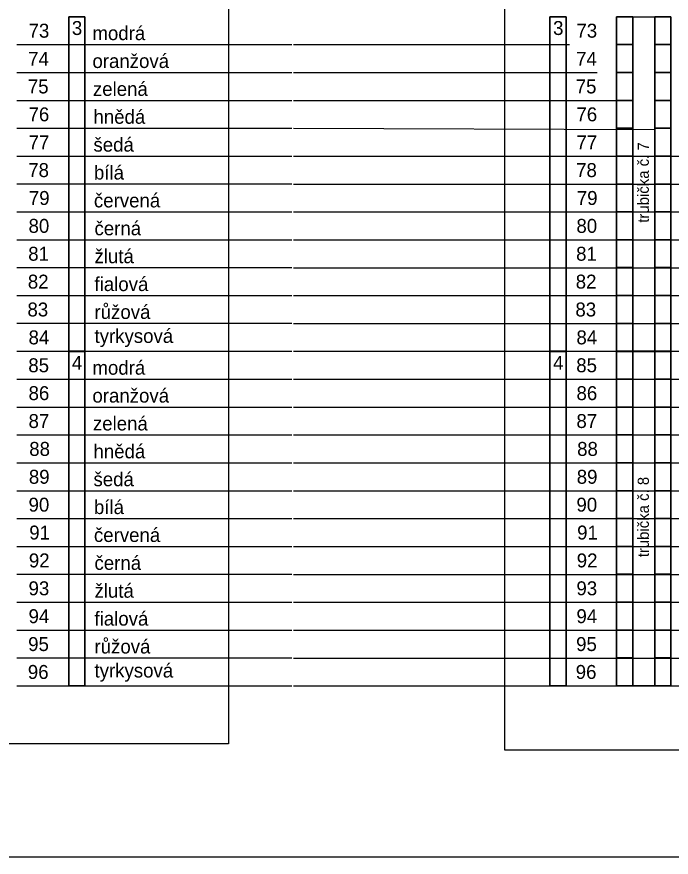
# Model space of a CAD drawing. Extents: x 1901 to 2519, y -3585 to -3154.
# Drawn here: x 2032.8 to 2115.5, y -3585 to -3478.9 of the extents above; entities that cross this region are included whole.
import ezdxf

# ---------------------------------------------------------------- set-up
doc = ezdxf.new("R2010")
doc.units = 0
doc.layers.add('rozvláknění', color=7, linetype='Continuous')
doc.layers.add('Vrstva 4', color=7, linetype='Continuous')

msp = doc.modelspace()

# ---------------------------------------------------------------- linework, layer by layer
at = {"layer": 'rozvláknění'}
for p, q in [((2032.82, -3482.38), (2067.53, -3482.38)), ((2067.76, -3482.38), (2102.61, -3482.38)), ((2032.82, -3485.9), (2067.53, -3485.9)), ((2067.76, -3485.9), (2106.13, -3485.9)), ((2032.82, -3489.42), (2067.53, -3489.42)), ((2067.76, -3489.42), (2109.65, -3489.42)), ((2032.82, -3492.94), (2067.53, -3492.94)), ((2067.76, -3492.94), (2113.34, -3493.1)), ((2032.82, -3496.46), (2067.53, -3496.46)), ((2067.76, -3496.46), (2116.69, -3496.46)), ((2032.82, -3499.97), (2067.53, -3499.97)), ((2067.76, -3499.98), (2120.21, -3499.98)), ((2032.82, -3503.49), (2067.53, -3503.49)), ((2067.76, -3503.5), (2123.73, -3503.5)), ((2032.82, -3507.01), (2067.53, -3507.01)), ((2067.76, -3507.02), (2127.25, -3507.02)), ((2032.82, -3510.53), (2067.53, -3510.53)), ((2067.76, -3510.54), (2130.77, -3510.54)), ((2032.82, -3514.05), (2067.53, -3514.05)), ((2067.76, -3514.06), (2134.29, -3514.06)), ((2032.82, -3517.56), (2067.53, -3517.56)), ((2067.76, -3517.58), (2137.81, -3517.58)), ((2032.82, -3521.1), (2067.53, -3521.1)), ((2067.76, -3521.1), (2141.33, -3521.1)), ((2032.82, -3524.62), (2067.53, -3524.62)), ((2067.76, -3524.62), (2144.85, -3524.62)), ((2032.82, -3528.14), (2067.53, -3528.14)), ((2067.76, -3528.14), (2148.37, -3528.14)), ((2032.82, -3531.66), (2067.53, -3531.66)), ((2067.76, -3531.66), (2151.89, -3531.66)), ((2032.82, -3535.18), (2067.53, -3535.18)), ((2067.76, -3535.18), (2155.41, -3535.18)), ((2032.82, -3538.7), (2067.53, -3538.7)), ((2067.76, -3538.7), (2215.14, -3538.7)), ((2032.82, -3542.21), (2067.53, -3542.21)), ((2067.76, -3542.22), (2218.66, -3542.22)), ((2032.82, -3545.73), (2067.53, -3545.73)), ((2067.76, -3545.74), (2222.18, -3545.74)), ((2032.82, -3549.25), (2067.53, -3549.25)), ((2067.76, -3549.26), (2225.7, -3549.26)), ((2032.82, -3552.77), (2067.53, -3552.77)), ((2067.76, -3552.78), (2229.22, -3552.78)), ((2032.82, -3556.29), (2067.53, -3556.29)), ((2067.76, -3556.3), (2232.74, -3556.3)), ((2032.82, -3559.8), (2067.53, -3559.8)), ((2067.76, -3559.82), (2236.26, -3559.82)), ((2032.82, -3563.34), (2067.53, -3563.34)), ((2067.76, -3563.34), (2239.78, -3563.34))]:
    msp.add_line(p, q, dxfattribs=at)
for points in [[(2014.87, -3178.54), (2059.52, -3178.54), (2059.52, -3570.66), (2014.87, -3570.66)], [(2094.46, -3178.54), (2128.46, -3178.54), (2128.46, -3571.47), (2094.46, -3571.47)], [(2041.39, -3563.34), (2039.35, -3563.34), (2039.35, -3478.87), (2041.39, -3478.87)], [(2041.39, -3521.08), (2039.35, -3521.08), (2039.35, -3478.87), (2041.39, -3478.87)], [(2102.19, -3521.08), (2100.14, -3521.08), (2100.14, -3478.87), (2102.19, -3478.87)], [(2108.57, -3478.87), (2110.61, -3478.87), (2110.61, -3482.38), (2108.57, -3482.38)], [(2108.57, -3478.87), (2110.61, -3478.87), (2110.61, -3482.38), (2108.57, -3482.38)], [(2110.61, -3478.87), (2113.39, -3478.87), (2113.39, -3521.08), (2110.61, -3521.08)], [(2113.39, -3478.87), (2115.43, -3478.87), (2115.43, -3482.38), (2113.39, -3482.38)], [(2113.39, -3478.87), (2115.43, -3478.87), (2115.43, -3482.38), (2113.39, -3482.38)], [(2108.57, -3482.38), (2110.61, -3482.38), (2110.61, -3485.9), (2108.57, -3485.9)], [(2108.57, -3482.38), (2110.61, -3482.38), (2110.61, -3485.9), (2108.57, -3485.9)], [(2113.39, -3482.38), (2115.43, -3482.38), (2115.43, -3485.9), (2113.39, -3485.9)], [(2113.39, -3482.38), (2115.43, -3482.38), (2115.43, -3485.9), (2113.39, -3485.9)], [(2108.57, -3485.9), (2110.61, -3485.9), (2110.61, -3489.42), (2108.57, -3489.42)], [(2108.57, -3485.9), (2110.61, -3485.9), (2110.61, -3489.42), (2108.57, -3489.42)], [(2113.39, -3485.9), (2115.43, -3485.9), (2115.43, -3489.42), (2113.39, -3489.42)], [(2113.39, -3485.9), (2115.43, -3485.9), (2115.43, -3489.42), (2113.39, -3489.42)], [(2108.57, -3489.42), (2110.61, -3489.42), (2110.61, -3492.94), (2108.57, -3492.94)], [(2108.57, -3489.42), (2110.61, -3489.42), (2110.61, -3492.94), (2108.57, -3492.94)], [(2113.39, -3489.42), (2115.43, -3489.42), (2115.43, -3492.94), (2113.39, -3492.94)], [(2113.39, -3489.42), (2115.43, -3489.42), (2115.43, -3492.94), (2113.39, -3492.94)], [(2108.57, -3492.94), (2110.61, -3492.94), (2110.61, -3496.46), (2108.57, -3496.46)], [(2108.57, -3492.94), (2110.61, -3492.94), (2110.61, -3496.46), (2108.57, -3496.46)], [(2113.39, -3492.94), (2115.43, -3492.94), (2115.43, -3496.46), (2113.39, -3496.46)], [(2113.39, -3492.94), (2115.43, -3492.94), (2115.43, -3496.46), (2113.39, -3496.46)], [(2108.57, -3496.46), (2110.61, -3496.46), (2110.61, -3499.98), (2108.57, -3499.98)], [(2108.57, -3496.46), (2110.61, -3496.46), (2110.61, -3499.98), (2108.57, -3499.98)], [(2113.39, -3496.46), (2115.43, -3496.46), (2115.43, -3499.98), (2113.39, -3499.98)], [(2113.39, -3496.46), (2115.43, -3496.46), (2115.43, -3499.98), (2113.39, -3499.98)], [(2108.57, -3499.98), (2110.61, -3499.98), (2110.61, -3503.49), (2108.57, -3503.49)], [(2108.57, -3499.98), (2110.61, -3499.98), (2110.61, -3503.49), (2108.57, -3503.49)], [(2113.39, -3499.98), (2115.43, -3499.98), (2115.43, -3503.49), (2113.39, -3503.49)], [(2113.39, -3499.98), (2115.43, -3499.98), (2115.43, -3503.49), (2113.39, -3503.49)], [(2108.57, -3503.49), (2110.61, -3503.49), (2110.61, -3507.01), (2108.57, -3507.01)], [(2108.57, -3503.49), (2110.61, -3503.49), (2110.61, -3507.01), (2108.57, -3507.01)], [(2113.39, -3503.49), (2115.43, -3503.49), (2115.43, -3507.01), (2113.39, -3507.01)], [(2113.39, -3503.49), (2115.43, -3503.49), (2115.43, -3507.01), (2113.39, -3507.01)], [(2108.57, -3507.01), (2110.61, -3507.01), (2110.61, -3510.53), (2108.57, -3510.53)], [(2108.57, -3507.01), (2110.61, -3507.01), (2110.61, -3510.53), (2108.57, -3510.53)], [(2113.39, -3507.01), (2115.43, -3507.01), (2115.43, -3510.53), (2113.39, -3510.53)], [(2113.39, -3507.01), (2115.43, -3507.01), (2115.43, -3510.53), (2113.39, -3510.53)], [(2108.57, -3510.53), (2110.61, -3510.53), (2110.61, -3514.05), (2108.57, -3514.05)], [(2108.57, -3510.53), (2110.61, -3510.53), (2110.61, -3514.05), (2108.57, -3514.05)], [(2113.39, -3510.53), (2115.43, -3510.53), (2115.43, -3514.05), (2113.39, -3514.05)], [(2113.39, -3510.53), (2115.43, -3510.53), (2115.43, -3514.05), (2113.39, -3514.05)], [(2108.57, -3514.05), (2110.61, -3514.05), (2110.61, -3517.57), (2108.57, -3517.57)], [(2108.57, -3514.05), (2110.61, -3514.05), (2110.61, -3517.57), (2108.57, -3517.57)], [(2113.39, -3514.05), (2115.43, -3514.05), (2115.43, -3517.57), (2113.39, -3517.57)], [(2113.39, -3514.05), (2115.43, -3514.05), (2115.43, -3517.57), (2113.39, -3517.57)], [(2108.57, -3517.57), (2110.61, -3517.57), (2110.61, -3521.08), (2108.57, -3521.08)], [(2108.57, -3517.57), (2110.61, -3517.57), (2110.61, -3521.08), (2108.57, -3521.08)], [(2113.39, -3517.57), (2115.43, -3517.57), (2115.43, -3521.08), (2113.39, -3521.08)], [(2113.39, -3517.57), (2115.43, -3517.57), (2115.43, -3521.08), (2113.39, -3521.08)], [(2041.39, -3563.32), (2039.35, -3563.32), (2039.35, -3521.11), (2041.39, -3521.11)], [(2102.19, -3563.32), (2100.14, -3563.32), (2100.14, -3521.11), (2102.19, -3521.11)], [(2108.57, -3521.11), (2110.61, -3521.11), (2110.61, -3524.62), (2108.57, -3524.62)], [(2108.57, -3521.11), (2110.61, -3521.11), (2110.61, -3524.62), (2108.57, -3524.62)], [(2110.61, -3521.11), (2113.39, -3521.11), (2113.39, -3563.32), (2110.61, -3563.32)], [(2113.39, -3521.11), (2115.43, -3521.11), (2115.43, -3524.62), (2113.39, -3524.62)], [(2113.39, -3521.11), (2115.43, -3521.11), (2115.43, -3524.62), (2113.39, -3524.62)], [(2108.57, -3524.62), (2110.61, -3524.62), (2110.61, -3528.14), (2108.57, -3528.14)], [(2108.57, -3524.62), (2110.61, -3524.62), (2110.61, -3528.14), (2108.57, -3528.14)], [(2113.39, -3524.62), (2115.43, -3524.62), (2115.43, -3528.14), (2113.39, -3528.14)], [(2113.39, -3524.62), (2115.43, -3524.62), (2115.43, -3528.14), (2113.39, -3528.14)], [(2108.57, -3528.14), (2110.61, -3528.14), (2110.61, -3531.66), (2108.57, -3531.66)], [(2108.57, -3528.14), (2110.61, -3528.14), (2110.61, -3531.66), (2108.57, -3531.66)], [(2113.39, -3528.14), (2115.43, -3528.14), (2115.43, -3531.66), (2113.39, -3531.66)], [(2113.39, -3528.14), (2115.43, -3528.14), (2115.43, -3531.66), (2113.39, -3531.66)], [(2108.57, -3531.66), (2110.61, -3531.66), (2110.61, -3535.18), (2108.57, -3535.18)], [(2108.57, -3531.66), (2110.61, -3531.66), (2110.61, -3535.18), (2108.57, -3535.18)], [(2113.39, -3531.66), (2115.43, -3531.66), (2115.43, -3535.18), (2113.39, -3535.18)], [(2113.39, -3531.66), (2115.43, -3531.66), (2115.43, -3535.18), (2113.39, -3535.18)], [(2108.57, -3535.18), (2110.61, -3535.18), (2110.61, -3538.7), (2108.57, -3538.7)], [(2108.57, -3535.18), (2110.61, -3535.18), (2110.61, -3538.7), (2108.57, -3538.7)], [(2113.39, -3535.18), (2115.43, -3535.18), (2115.43, -3538.7), (2113.39, -3538.7)], [(2113.39, -3535.18), (2115.43, -3535.18), (2115.43, -3538.7), (2113.39, -3538.7)], [(2108.57, -3538.7), (2110.61, -3538.7), (2110.61, -3542.22), (2108.57, -3542.22)], [(2108.57, -3538.7), (2110.61, -3538.7), (2110.61, -3542.22), (2108.57, -3542.22)], [(2113.39, -3538.7), (2115.43, -3538.7), (2115.43, -3542.22), (2113.39, -3542.22)], [(2113.39, -3538.7), (2115.43, -3538.7), (2115.43, -3542.22), (2113.39, -3542.22)], [(2108.57, -3542.22), (2110.61, -3542.22), (2110.61, -3545.73), (2108.57, -3545.73)], [(2108.57, -3542.22), (2110.61, -3542.22), (2110.61, -3545.73), (2108.57, -3545.73)], [(2113.39, -3542.22), (2115.43, -3542.22), (2115.43, -3545.73), (2113.39, -3545.73)], [(2113.39, -3542.22), (2115.43, -3542.22), (2115.43, -3545.73), (2113.39, -3545.73)], [(2108.57, -3545.73), (2110.61, -3545.73), (2110.61, -3549.25), (2108.57, -3549.25)], [(2108.57, -3545.73), (2110.61, -3545.73), (2110.61, -3549.25), (2108.57, -3549.25)], [(2113.39, -3545.73), (2115.43, -3545.73), (2115.43, -3549.25), (2113.39, -3549.25)], [(2113.39, -3545.73), (2115.43, -3545.73), (2115.43, -3549.25), (2113.39, -3549.25)], [(2108.57, -3549.25), (2110.61, -3549.25), (2110.61, -3552.77), (2108.57, -3552.77)], [(2108.57, -3549.25), (2110.61, -3549.25), (2110.61, -3552.77), (2108.57, -3552.77)], [(2113.39, -3549.25), (2115.43, -3549.25), (2115.43, -3552.77), (2113.39, -3552.77)], [(2113.39, -3549.25), (2115.43, -3549.25), (2115.43, -3552.77), (2113.39, -3552.77)], [(2108.57, -3552.77), (2110.61, -3552.77), (2110.61, -3556.29), (2108.57, -3556.29)], [(2108.57, -3552.77), (2110.61, -3552.77), (2110.61, -3556.29), (2108.57, -3556.29)], [(2113.39, -3552.77), (2115.43, -3552.77), (2115.43, -3556.29), (2113.39, -3556.29)], [(2113.39, -3552.77), (2115.43, -3552.77), (2115.43, -3556.29), (2113.39, -3556.29)], [(2108.57, -3556.29), (2110.61, -3556.29), (2110.61, -3559.81), (2108.57, -3559.81)], [(2108.57, -3556.29), (2110.61, -3556.29), (2110.61, -3559.81), (2108.57, -3559.81)], [(2113.39, -3556.29), (2115.43, -3556.29), (2115.43, -3559.81), (2113.39, -3559.81)], [(2113.39, -3556.29), (2115.43, -3556.29), (2115.43, -3559.81), (2113.39, -3559.81)], [(2108.57, -3559.81), (2110.61, -3559.81), (2110.61, -3563.32), (2108.57, -3563.32)], [(2108.57, -3559.81), (2110.61, -3559.81), (2110.61, -3563.32), (2108.57, -3563.32)], [(2113.39, -3559.81), (2115.43, -3559.81), (2115.43, -3563.32), (2113.39, -3563.32)], [(2113.39, -3559.81), (2115.43, -3559.81), (2115.43, -3563.32), (2113.39, -3563.32)]]:
    msp.add_lwpolyline(points, close=True, dxfattribs=at)
for points in [[(2041.39, -3478.87), (2039.35, -3478.87), (2039.35, -3521.08), (2041.39, -3521.08), (2041.39, -3478.87)], [(2102.19, -3478.87), (2100.14, -3478.87), (2100.14, -3521.08), (2102.19, -3521.08), (2102.19, -3478.87)], [(2108.57, -3482.38), (2110.61, -3482.38), (2110.61, -3478.87), (2108.57, -3478.87), (2108.57, -3482.38)], [(2113.39, -3482.38), (2115.43, -3482.38), (2115.43, -3478.87), (2113.39, -3478.87), (2113.39, -3482.38)], [(2108.57, -3485.9), (2110.61, -3485.9), (2110.61, -3482.38), (2108.57, -3482.38), (2108.57, -3485.9)], [(2113.39, -3485.9), (2115.43, -3485.9), (2115.43, -3482.38), (2113.39, -3482.38), (2113.39, -3485.9)], [(2108.57, -3489.42), (2110.61, -3489.42), (2110.61, -3485.9), (2108.57, -3485.9), (2108.57, -3489.42)], [(2113.39, -3489.42), (2115.43, -3489.42), (2115.43, -3485.9), (2113.39, -3485.9), (2113.39, -3489.42)], [(2108.57, -3492.94), (2110.61, -3492.94), (2110.61, -3489.42), (2108.57, -3489.42), (2108.57, -3492.94)], [(2113.39, -3492.94), (2115.43, -3492.94), (2115.43, -3489.42), (2113.39, -3489.42), (2113.39, -3492.94)], [(2108.57, -3496.46), (2110.61, -3496.46), (2110.61, -3492.94), (2108.57, -3492.94), (2108.57, -3496.46)], [(2113.39, -3496.46), (2115.43, -3496.46), (2115.43, -3492.94), (2113.39, -3492.94), (2113.39, -3496.46)], [(2108.57, -3499.98), (2110.61, -3499.98), (2110.61, -3496.46), (2108.57, -3496.46), (2108.57, -3499.98)], [(2113.39, -3499.98), (2115.43, -3499.98), (2115.43, -3496.46), (2113.39, -3496.46), (2113.39, -3499.98)], [(2108.57, -3503.49), (2110.61, -3503.49), (2110.61, -3499.98), (2108.57, -3499.98), (2108.57, -3503.49)], [(2113.39, -3503.49), (2115.43, -3503.49), (2115.43, -3499.98), (2113.39, -3499.98), (2113.39, -3503.49)], [(2108.57, -3507.01), (2110.61, -3507.01), (2110.61, -3503.49), (2108.57, -3503.49), (2108.57, -3507.01)], [(2113.39, -3507.01), (2115.43, -3507.01), (2115.43, -3503.49), (2113.39, -3503.49), (2113.39, -3507.01)], [(2108.57, -3510.53), (2110.61, -3510.53), (2110.61, -3507.01), (2108.57, -3507.01), (2108.57, -3510.53)], [(2113.39, -3510.53), (2115.43, -3510.53), (2115.43, -3507.01), (2113.39, -3507.01), (2113.39, -3510.53)], [(2108.57, -3514.05), (2110.61, -3514.05), (2110.61, -3510.53), (2108.57, -3510.53), (2108.57, -3514.05)], [(2113.39, -3514.05), (2115.43, -3514.05), (2115.43, -3510.53), (2113.39, -3510.53), (2113.39, -3514.05)], [(2108.57, -3517.57), (2110.61, -3517.57), (2110.61, -3514.05), (2108.57, -3514.05), (2108.57, -3517.57)], [(2113.39, -3517.57), (2115.43, -3517.57), (2115.43, -3514.05), (2113.39, -3514.05), (2113.39, -3517.57)], [(2108.57, -3521.08), (2110.61, -3521.08), (2110.61, -3517.57), (2108.57, -3517.57), (2108.57, -3521.08)], [(2113.39, -3521.08), (2115.43, -3521.08), (2115.43, -3517.57), (2113.39, -3517.57), (2113.39, -3521.08)], [(2041.39, -3521.11), (2039.35, -3521.11), (2039.35, -3563.32), (2041.39, -3563.32), (2041.39, -3521.11)], [(2102.19, -3521.11), (2100.14, -3521.11), (2100.14, -3563.32), (2102.19, -3563.32), (2102.19, -3521.11)], [(2108.57, -3524.62), (2110.61, -3524.62), (2110.61, -3521.11), (2108.57, -3521.11), (2108.57, -3524.62)], [(2113.39, -3524.62), (2115.43, -3524.62), (2115.43, -3521.11), (2113.39, -3521.11), (2113.39, -3524.62)], [(2108.57, -3528.14), (2110.61, -3528.14), (2110.61, -3524.62), (2108.57, -3524.62), (2108.57, -3528.14)], [(2113.39, -3528.14), (2115.43, -3528.14), (2115.43, -3524.62), (2113.39, -3524.62), (2113.39, -3528.14)], [(2108.57, -3531.66), (2110.61, -3531.66), (2110.61, -3528.14), (2108.57, -3528.14), (2108.57, -3531.66)], [(2113.39, -3531.66), (2115.43, -3531.66), (2115.43, -3528.14), (2113.39, -3528.14), (2113.39, -3531.66)], [(2108.57, -3535.18), (2110.61, -3535.18), (2110.61, -3531.66), (2108.57, -3531.66), (2108.57, -3535.18)], [(2113.39, -3535.18), (2115.43, -3535.18), (2115.43, -3531.66), (2113.39, -3531.66), (2113.39, -3535.18)], [(2108.57, -3538.7), (2110.61, -3538.7), (2110.61, -3535.18), (2108.57, -3535.18), (2108.57, -3538.7)], [(2113.39, -3538.7), (2115.43, -3538.7), (2115.43, -3535.18), (2113.39, -3535.18), (2113.39, -3538.7)], [(2108.57, -3542.22), (2110.61, -3542.22), (2110.61, -3538.7), (2108.57, -3538.7), (2108.57, -3542.22)], [(2113.39, -3542.22), (2115.43, -3542.22), (2115.43, -3538.7), (2113.39, -3538.7), (2113.39, -3542.22)], [(2108.57, -3545.73), (2110.61, -3545.73), (2110.61, -3542.22), (2108.57, -3542.22), (2108.57, -3545.73)], [(2113.39, -3545.73), (2115.43, -3545.73), (2115.43, -3542.22), (2113.39, -3542.22), (2113.39, -3545.73)], [(2108.57, -3549.25), (2110.61, -3549.25), (2110.61, -3545.73), (2108.57, -3545.73), (2108.57, -3549.25)], [(2113.39, -3549.25), (2115.43, -3549.25), (2115.43, -3545.73), (2113.39, -3545.73), (2113.39, -3549.25)], [(2108.57, -3552.77), (2110.61, -3552.77), (2110.61, -3549.25), (2108.57, -3549.25), (2108.57, -3552.77)], [(2113.39, -3552.77), (2115.43, -3552.77), (2115.43, -3549.25), (2113.39, -3549.25), (2113.39, -3552.77)], [(2108.57, -3556.29), (2110.61, -3556.29), (2110.61, -3552.77), (2108.57, -3552.77), (2108.57, -3556.29)], [(2113.39, -3556.29), (2115.43, -3556.29), (2115.43, -3552.77), (2113.39, -3552.77), (2113.39, -3556.29)], [(2108.57, -3559.81), (2110.61, -3559.81), (2110.61, -3556.29), (2108.57, -3556.29), (2108.57, -3559.81)], [(2113.39, -3559.81), (2115.43, -3559.81), (2115.43, -3556.29), (2113.39, -3556.29), (2113.39, -3559.81)], [(2108.57, -3563.32), (2110.61, -3563.32), (2110.61, -3559.81), (2108.57, -3559.81), (2108.57, -3563.32)], [(2113.39, -3563.32), (2115.43, -3563.32), (2115.43, -3559.81), (2113.39, -3559.81), (2113.39, -3563.32)]]:
    msp.add_lwpolyline(points, dxfattribs=at)
at = {"layer": 'Vrstva 4'}
msp.add_lwpolyline([(1901.22, -3154.47), (2516.22, -3154.47), (2516.22, -3584.97), (1901.22, -3584.97)], close=True, dxfattribs=at)

# ---------------------------------------------------------------- texts
at = {"layer": 'rozvláknění'}
for s, p in [('73', (2034.28, -3481.5)), ('3', (2039.75, -3481.16)), ('3', (2039.75, -3481.16)), ('modrá', (2042.35, -3481.81)), ('3', (2100.54, -3481.16)), ('73', (2103.49, -3481.5)), ('74', (2034.23, -3485.05)), ('74', (2103.45, -3485.05)), ('oranžová', (2042.35, -3485.33)), ('75', (2034.19, -3488.54)), ('zelená', (2042.41, -3488.85)), ('75', (2103.4, -3488.54)), ('76', (2034.28, -3492.06)), ('hnědá', (2042.48, -3492.37)), ('76', (2103.49, -3492.06)), ('77', (2034.28, -3495.61)), ('77', (2103.49, -3495.61)), ('šedá', (2042.48, -3495.89)), ('78', (2034.24, -3499.1)), ('bílá', (2042.54, -3499.41)), ('78', (2103.45, -3499.1)), ('79', (2034.32, -3502.62)), ('červená', (2042.54, -3502.93)), ('79', (2103.54, -3502.62)), ('80', (2034.28, -3506.14)), ('80', (2103.49, -3506.14)), ('černá', (2042.61, -3506.45)), ('81', (2034.24, -3509.66)), ('žlutá', (2042.61, -3509.97)), ('81', (2103.45, -3509.66)), ('82', (2034.19, -3513.18)), ('fialová', (2042.61, -3513.49)), ('82', (2103.4, -3513.18)), ('83', (2034.14, -3516.7)), ('růžová', (2042.61, -3517.01)), ('83', (2103.36, -3516.7)), ('tyrkysová', (2042.61, -3520.04)), ('84', (2034.28, -3520.22)), ('84', (2103.49, -3520.22)), ('85', (2034.25, -3523.74)), ('4', (2039.75, -3523.43)), ('4', (2039.75, -3523.43)), ('modrá', (2042.35, -3524.05)), ('4', (2100.54, -3523.43)), ('85', (2103.47, -3523.74)), ('86', (2034.28, -3527.26)), ('oranžová', (2042.35, -3527.57)), ('86', (2103.5, -3527.26)), ('87', (2034.28, -3530.78)), ('zelená', (2042.41, -3531.09)), ('87', (2103.49, -3530.78)), ('88', (2034.37, -3534.3)), ('hnědá', (2042.48, -3534.61)), ('88', (2103.58, -3534.3)), ('89', (2034.32, -3537.82)), ('šedá', (2042.48, -3538.13)), ('89', (2103.53, -3537.82)), ('90', (2034.28, -3541.34)), ('90', (2103.49, -3541.34)), ('bílá', (2042.54, -3541.65)), ('91', (2034.37, -3544.86)), ('červená', (2042.54, -3545.17)), ('91', (2103.58, -3544.86)), ('92', (2034.32, -3548.38)), ('černá', (2042.61, -3548.69)), ('92', (2103.53, -3548.38)), ('93', (2034.28, -3551.9)), ('93', (2103.49, -3551.9)), ('žlutá', (2042.61, -3552.21)), ('94', (2034.28, -3555.42)), ('fialová', (2042.61, -3555.73)), ('94', (2103.49, -3555.42)), ('95', (2034.23, -3558.94)), ('růžová', (2042.61, -3559.25)), ('95', (2103.45, -3558.94)), ('96', (2034.19, -3562.46)), ('tyrkysová', (2042.61, -3562.28)), ('96', (2103.4, -3562.46))]:
    msp.add_text(s, height=1.76, dxfattribs=at).set_placement(p)
for s, p in [('trubička č. 7', (2112.64, -3504.86)), ('trubička č. 8', (2112.64, -3547.1))]:
    msp.add_text(s, height=1.408, rotation=90, dxfattribs=at).set_placement(p)

doc.saveas('drawing.dxf')
